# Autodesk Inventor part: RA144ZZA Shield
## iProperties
Category: PARTsolutions
Created: 2011-07
Part Number: RA144ZZA Shield
Catalog Web Link: www.cadenas.de
Description: Six types s - Inch system sizes
Document SubType Name: Modeling
Designer: PARTsolutions
Density: 1 g/cm^3
NB: RA144ZZA Shield
NN: Six types s
NT: Inch system sizes
NBSYN: RA144ZZA Shield
LINA: RA144ZZA Shield
SD: 3.175
D: 6.350
B: 2.380
B1: 2.779
D1: 7.52
D2: 7.52
C1: 0.58
C2: 0.79
R: 0.08
ORDER: RA144ZZA
CR: 284
COR: 96
CRF: 29
CORF: 10
LSG: 59000
LSO: 70000
MASS: 0.27
ORDER1: R144
WSS: RA144ZA
WDS: RA144ZZA
UTWF: FLR144
FORSS: FLRA144ZA
FORDS: FLRA144ZZA
DA1: 3.9
DA2: 4
DA: 5.5
RAS: 0.08
MASS1: 0.33
VERS: 3
X: 1.587
N: 9
O: 14.954
RB: 0.470
KT: DUMMY
SUPPLIER: NTN
ARTICLENO: RA144ZZA Shield
BOMINFO: RA144ZZA Shield
CREATOR: CADENAS GmbH
PSOL_IDENT_0: {\\10.0.0.251\ps_data\23d-libs\ntn\ball_roller_bearings\miniature_extra_small_bb\inch_system_sizes\i
PSOL_IDENT_1: ss_s.prj},180 {VTYP=3D},{NB=RA144ZZA Shield},{LINA=RA144ZZA Shield},{NN=Six types s},{DATE=11.12.200
PSOL_IDENT_2: 7 08:48:22},{GEOMDATE=02.04.2007 13:01:00},{VERSION=},{LINEID=16080},{LINESUBID=-1},{WBVAR=}  {NB=RA
PSOL_IDENT_3: 144ZZA Shield},{LINA=RA144ZZA Shield},{KT=DUMMY},{IDNR=},{SD=3.175},{D=6.350},{B=2.380},{B1=2.779},{
PSOL_IDENT_4: D1=7.52},{D2=7.52},{C1=0.58},{C2=0.79},{R=0.08},{ORDER=RA144ZZA},{CR=284},{COR=96},{CRF=29},{CORF=10
PSOL_IDENT_5: },{LSG=59000},{LSO=70000},{MASS=0.27},{ORDER1=R144},{WSS=RA144ZA},{WDS=RA144ZZA},{UTWF=FLR144},{FORS
PSOL_IDENT_6: S=FLRA144ZA},{FORDS=FLRA144ZZA},{DA1=3.9},{DA2=4},{DA=5.5},{RAS=0.08},{MASS1=0.33},{VERS=3},{X=1.587
PSOL_IDENT_7: 5},{N=9},{O=14.95425},{RB=0.4699}
Title: RA144ZZA Shield
Author: Cadenas PARTsolutions
Comments: Inch system sizes
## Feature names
1. Revolution1
